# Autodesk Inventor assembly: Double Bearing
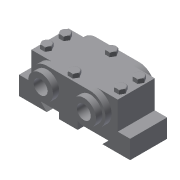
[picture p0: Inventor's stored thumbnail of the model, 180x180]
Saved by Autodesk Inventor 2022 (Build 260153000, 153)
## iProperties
Created: 2002-02
Part Number: Double Bearing
Document SubType Name: Assembly
Designer: ***
Control State: 0
Master: False
Checked Out: False
Shininess: 64.0
Length Units: 11269
Angle Units: 11279
Time Units: 11290
Mass Units: 11283
Length Display Precision: 3
Angle Display Precision: 2
Density: 0.0
Volumn: 0.0
Area: 0.0
PropertySet Name: Model Information
Author: ***
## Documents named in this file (5)
- D:\PROJECTS_2021\Resources\Tutorial Files\c12_Inv_2021_tut\c12_Inv_tut_2021\c12_tut02_inv\Double Bearing.iam
- D:\PROJECTS_2021\Resources\Tutorial Files\c12_Inv_2021_tut\c12_Inv_tut_2021\c12_tut02_inv\Base.ipt
- D:\PROJECTS_2021\Resources\Tutorial Files\c12_Inv_2021_tut\c12_Inv_tut_2021\c12_tut02_inv\Cap.ipt
- D:\PROJECTS_2021\Resources\Tutorial Files\c12_Inv_2021_tut\c12_Inv_tut_2021\c12_tut02_inv\Bushing.ipt
- D:\PROJECTS_2021\Resources\Tutorial Files\c12_Inv_2021_tut\c12_Inv_tut_2021\c12_tut02_inv\Bolt.ipt
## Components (10 placed, 4 different names)
1. Base:1 — Insert:1, Insert:2
2. Cap:1 — Insert:1, Insert:2, Insert:3, Insert:4, Insert:5, Insert:6
3. Bushing:1 — Insert:3
4. Bushing:2 — Insert:4
5. Bolt:1 — Insert:5
6. Bolt:6
7. Bolt:7
8. Bolt:8
9. Bolt:5 — Insert:6
10. Bolt:9
## Component patterns: Component Pattern 1 (4 elements), Component Pattern 2 (2 elements)
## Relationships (6: Insert 6)
- Insert:1: Base:1 ↔ Cap:1
- Insert:2: Base:1 ↔ Cap:1
- Insert:3: Cap:1 ↔ Bushing:1
- Insert:4: Cap:1 ↔ Bushing:2
- Insert:5: Cap:1 ↔ Bolt:1
- Insert:6: Cap:1 ↔ Bolt:5
